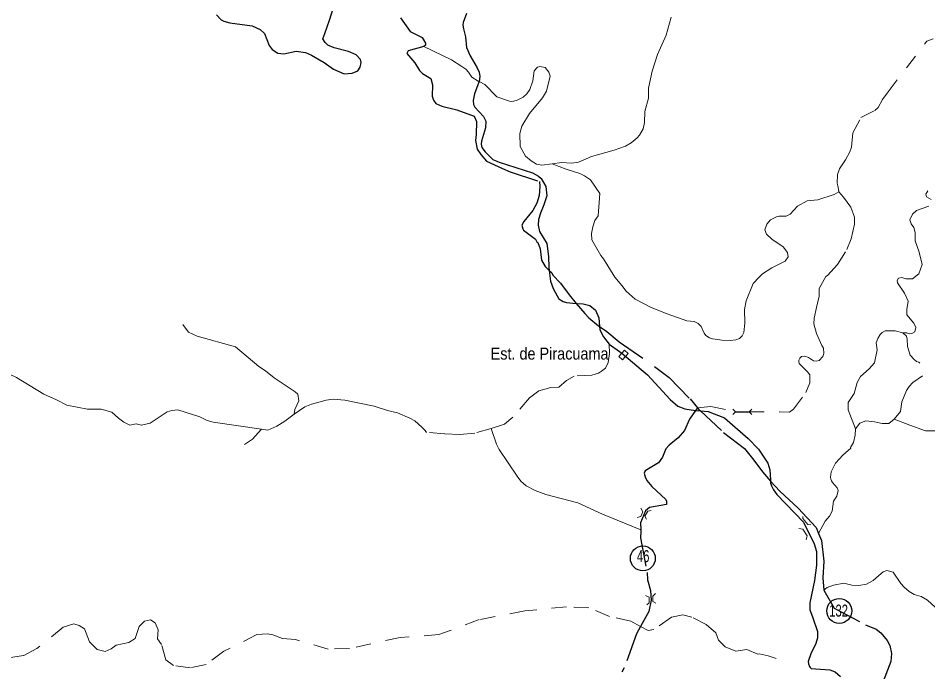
# Model space of a CAD drawing. Extents: x 423 to 448.8, y 7456.3 to 7484.
# Drawn here: x 434.76 to 440.83, y 7470.29 to 7474.65 of the extents above; entities that cross this region are included whole.
import ezdxf
from ezdxf.enums import TextEntityAlignment as Align

# ---------------------------------------------------------------- set-up
doc = ezdxf.new("R2010")
doc.units = 0
doc.header["$LTSCALE"] = 0.032
doc.linetypes.add('LONG_DASHED', pattern=[7.5, 6, -1.5])
doc.linetypes.add('MEDIUM_DASHED', pattern=[4.5, 3, -1.5])
for name, color, linetype, lineweight in [('11', 7, 'Continuous', 13), ('13', 7, 'Continuous', 25), ('15', 7, 'Continuous', 25), ('28', 7, 'Continuous', 25), ('31', 7, 'Continuous', 25), ('4', 7, 'LONG_DASHED', 25), ('6', 7, 'MEDIUM_DASHED', 13), ('7', 7, 'Continuous', 13)]:
    doc.layers.add(name, color=color, linetype=linetype, lineweight=lineweight)
doc.layers.add('61', color=7, linetype='Continuous')

msp = doc.modelspace()

# ---------------------------------------------------------------- linework, layer by layer
at = {"layer": '11'}
for points in [[(438.9162, 7471.3779), (438.93, 7471.3542), (438.9162, 7471.3236), (438.8915, 7471.3157)], [(438.9546, 7471.3058), (438.9428, 7471.3246), (438.9625, 7471.3591), (438.9852, 7471.364)], [(439.9969, 7471.3244), (439.9971, 7471.3106), (440.0308, 7471.269), (440.0512, 7471.2679)], [(439.9695, 7471.2426), (439.9963, 7471.2391), (440.0259, 7471.1952), (440.0195, 7471.168)], [(438.9477, 7470.7958), (438.9714, 7470.784), (438.9714, 7470.7475), (438.9566, 7470.7347)], [(439.0148, 7470.8086), (438.9961, 7470.7919), (438.9971, 7470.7554), (439.0158, 7470.7445)]]:
    msp.add_lwpolyline(points, dxfattribs=at)
at = {"layer": '13'}
for centre in [(438.9294, 7471.0434), (440.24, 7470.6931)]:
    msp.add_circle(centre, 0.083, dxfattribs=at)
at = {"layer": '15'}
for points in [[(436.0839, 7474.673), (436.1165, 7474.6386), (436.1328, 7474.6291), (436.1741, 7474.6188), (436.3235, 7474.5991), (436.3751, 7474.575), (436.4045, 7474.5469), (436.4353, 7474.4682), (436.4566, 7474.441), (436.4936, 7474.417), (436.534, 7474.4127), (436.6155, 7474.429), (436.6774, 7474.4196), (436.7186, 7474.4033), (436.8027, 7474.3543), (436.8654, 7474.3096), (436.9376, 7474.2775), (436.9889, 7474.2833), (437.0267, 7474.2982), (437.0436, 7474.3222), (437.0506, 7474.3541), (437.0466, 7474.375), (437.0162, 7474.4055), (436.9645, 7474.4284), (436.8689, 7474.4513), (436.8266, 7474.4688), (436.8087, 7474.4868), (436.7943, 7474.5116), (436.8072, 7474.5465), (436.838, 7474.6368), (436.868, 7474.7279)], [(437.7535, 7474.6807), (437.7315, 7474.6205), (437.7294, 7474.6042)], [(437.7294, 7474.6042), (437.7317, 7474.5789), (437.7466, 7474.5261), (437.7535, 7474.4548), (437.7779, 7474.3977), (437.8239, 7474.3191), (437.8367, 7474.2895), (437.842, 7474.2609), (437.8363, 7474.2266), (437.8357, 7474.2228), (437.8283, 7474.2048), (437.806, 7474.1445), (437.7981, 7474.0992), (437.7986, 7474.0746), (437.8081, 7474.0556), (437.8667, 7473.9928), (437.8807, 7473.9619), (437.8787, 7473.917), (437.8523, 7473.8279), (437.8515, 7473.8079), (437.8557, 7473.7866), (437.8769, 7473.7581), (437.9047, 7473.7299), (437.9288, 7473.7063), (437.9699, 7473.6888), (438.1924, 7473.6165), (438.2336, 7473.5951), (438.2499, 7473.5805), (438.2832, 7473.5264), (438.2894, 7473.4645), (438.2697, 7473.4036), (438.247, 7473.3479), (438.2327, 7473.3059), (438.2301, 7473.2679), (438.2404, 7473.2267), (438.2879, 7473.145), (438.3006, 7473.06), (438.3031, 7472.9863), (438.3054, 7472.9658), (438.3136, 7472.8943), (438.3315, 7472.8453), (438.3569, 7472.7962), (438.3691, 7472.777), (438.3982, 7472.7581), (438.4208, 7472.7508), (438.4853, 7472.7461), (438.492, 7472.7456), (438.5317, 7472.7432), (438.5766, 7472.7316), (438.6126, 7472.7001), (438.6357, 7472.6495), (438.6405, 7472.5912), (438.6423, 7472.5702), (438.6667, 7472.5221), (438.7042, 7472.4735), (438.7898, 7472.4142), (438.9602, 7472.2682), (439.1113, 7472.105), (439.1637, 7472.0597), (439.2095, 7472.0417), (439.2815, 7472.0304), (439.3137, 7472.0277), (439.3653, 7472.0235), (439.4733, 7471.9812), (439.6318, 7471.8448), (439.7014, 7471.7717), (439.7631, 7471.6803), (439.7775, 7471.6352), (439.7815, 7471.5689), (439.7818, 7471.5602), (439.7822, 7471.5471), (439.7847, 7471.5356), (439.7883, 7471.5274), (439.8005, 7471.5006), (439.8229, 7471.4699), (440.0013, 7471.285), (440.0732, 7471.1414), (440.087, 7471.0899), (440.088, 7470.9977), (440.0741, 7470.8958), (440.0432, 7470.7463), (440.044, 7470.6999), (440.0604, 7470.6528), (440.0947, 7470.5548), (440.0938, 7470.5144), (440.0844, 7470.4766), (440.0492, 7470.4062), (440.032, 7470.3555), (440.0346, 7470.3392), (440.042, 7470.3227), (440.0465, 7470.3147), (440.0528, 7470.3085), (440.1763, 7470.3006), (440.2123, 7470.2868), (440.2492, 7470.2546)]]:
    msp.add_lwpolyline(points, dxfattribs=at)
at = {"layer": '28'}
msp.add_lwpolyline([(438.7687, 7472.3921), (438.8069, 7472.4344), (438.832, 7472.4117), (438.7938, 7472.3694)], close=True, dxfattribs=at)
at = {"layer": '31'}
for p, q in [((439.5469, 7472.0219), (439.5294, 7472.0396)), ((439.6394, 7472.0219), (439.6571, 7472.0396)), ((439.5294, 7472.0043), (439.5469, 7472.0219)), ((439.5469, 7472.0219), (439.6394, 7472.0219)), ((439.6571, 7472.0043), (439.6394, 7472.0219))]:
    msp.add_line(p, q, dxfattribs=at)
at = {"layer": '4'}
for points in [[(437.312, 7474.6514), (437.3773, 7474.5613), (437.4572, 7474.5218), (437.4787, 7474.4823), (437.4787, 7474.4702), (437.4691, 7474.4617), (437.3636, 7474.4316), (437.3542, 7474.4133), (437.4086, 7474.3522), (437.4383, 7474.3002), (437.4589, 7474.2813), (437.5147, 7474.2478), (437.525, 7474.204), (437.5233, 7474.1284), (437.5319, 7474.1027), (437.5482, 7474.0812), (437.5878, 7474.0614), (437.6891, 7474.0374), (437.8033, 7473.9962), (437.8187, 7473.9593), (437.8174, 7473.8738), (437.8129, 7473.8338), (437.8245, 7473.7756), (437.849, 7473.7396), (437.8853, 7473.6949), (437.9939, 7473.6458), (438.0446, 7473.6236), (438.2396, 7473.5599), (438.2419, 7473.5267), (438.237, 7473.4654), (438.2216, 7473.4156), (438.1958, 7473.3658), (438.1348, 7473.2919), (438.1219, 7473.2679), (438.1288, 7473.2438), (438.1331, 7473.2344), (438.213, 7473.1751), (438.2216, 7473.1579), (438.2293, 7473.1528), (438.2439, 7473.1099), (438.2524, 7473.0353), (438.2771, 7472.9919), (438.3054, 7472.9658), (438.3222, 7472.9503), (438.3289, 7472.9346), (438.3796, 7472.8814), (438.438, 7472.8024), (438.4853, 7472.7461), (438.5419, 7472.6787), (438.5685, 7472.6503), (438.6329, 7472.5963), (438.6405, 7472.5912), (438.6901, 7472.5585), (438.7721, 7472.4897), (439.0074, 7472.3257), (439.1045, 7472.2501), (439.2444, 7472.1084), (439.2944, 7472.0483)], [(439.2942, 7472.0483), (439.2815, 7472.0304), (439.2417, 7471.9739), (439.2078, 7471.8982), (439.1661, 7471.8487), (439.1044, 7471.7993), (439.083, 7471.776), (439.0606, 7471.7203), (439.0332, 7471.6824), (438.9447, 7471.6292), (438.9387, 7471.612), (438.9438, 7471.588), (438.9559, 7471.5639), (438.9894, 7471.5227), (439.0821, 7471.4359), (439.0881, 7471.4248), (439.0873, 7471.4025), (438.9727, 7471.3829), (438.9463, 7471.3601), (438.9128, 7471.2818), (438.915, 7471.2343)], [(439.2944, 7472.0483), (439.3037, 7472.0371), (439.3137, 7472.0277), (439.4669, 7471.8843), (439.6086, 7471.7769), (439.6706, 7471.6991), (439.7273, 7471.6211), (439.7818, 7471.5602), (439.8431, 7471.4917), (439.9658, 7471.3787), (440.085, 7471.2503), (440.1025, 7471.2099), (440.1223, 7471.1642), (440.1359, 7471.0246), (440.1299, 7470.9147), (440.1376, 7470.8322), (440.2053, 7470.7115), (440.414, 7470.6004), (440.4855, 7470.5702), (440.5181, 7470.5462), (440.5602, 7470.4955), (440.5773, 7470.4612), (440.5876, 7470.4097), (440.5851, 7470.3547), (440.5207, 7470.1932)], [(438.915, 7471.2343), (438.9156, 7471.2221), (438.9146, 7471.1809), (438.9577, 7470.9493), (438.9611, 7470.9016), (438.9815, 7470.8301), (438.985, 7470.7653), (438.9688, 7470.6898), (438.914, 7470.5894), (438.8869, 7470.5397), (438.8051, 7470.3134), (438.7902, 7470.2846)]]:
    msp.add_lwpolyline(points, dxfattribs=at)
at = {"layer": '6'}
for points in [[(439.2942, 7472.0483), (439.2944, 7472.0483), (439.3822, 7472.0584), (439.5469, 7472.0219), (439.6394, 7472.0219), (439.8405, 7472.0216), (439.9083, 7472.0205), (439.9352, 7472.0398), (440.0159, 7472.1507), (440.0433, 7472.2145), (440.0433, 7472.2699), (440.0281, 7472.2893), (439.9838, 7472.3336), (439.973, 7472.3445), (439.9695, 7472.3575), (439.9697, 7472.3673), (439.9758, 7472.3801), (439.9883, 7472.3912), (440.0106, 7472.3928), (440.0347, 7472.384), (440.0678, 7472.3617), (440.0856, 7472.3593), (440.1061, 7472.3651), (440.1312, 7472.3908), (440.1369, 7472.4107), (440.134, 7472.4462), (440.1228, 7472.4639), (440.0872, 7472.545), (440.0707, 7472.6096), (440.0718, 7472.6473), (440.0878, 7472.7193), (440.105, 7472.7936), (440.1058, 7472.8445), (440.1511, 7472.9259), (440.1617, 7472.9312), (440.2287, 7473.0059), (440.2905, 7473.1064), (440.3197, 7473.1777), (440.3412, 7473.2756), (440.3421, 7473.3211), (440.3171, 7473.3881), (440.2673, 7473.4559), (440.2374, 7473.4897), (440.2369, 7473.4954), (440.23, 7473.5303), (440.2259, 7473.5492), (440.2277, 7473.6055), (440.2415, 7473.6435), (440.2813, 7473.7033), (440.3107, 7473.7576), (440.3216, 7473.7885), (440.3301, 7473.8836), (440.3843, 7473.9857), (440.4779, 7474.0346), (440.4993, 7474.054), (440.5282, 7474.1078), (440.5655, 7474.1592), (440.8247, 7474.496), (440.8659, 7474.5115)], [(438.7042, 7472.4735), (438.7063, 7472.4121), (438.6984, 7472.3507), (438.6796, 7472.3132), (438.6541, 7472.2942), (438.6324, 7472.2797), (438.5899, 7472.2673), (438.4713, 7472.2601), (438.419, 7472.2317), (438.3683, 7472.1869), (438.3145, 7472.1839), (438.2361, 7472.1615), (438.1735, 7472.1152), (438.0622, 7471.9866), (438.0055, 7471.9388), (437.9179, 7471.9118), (437.8078, 7471.879), (437.7083, 7471.8714), (437.6056, 7471.8761), (437.4863, 7471.8844), (437.4779, 7471.8963)], [(440.7956, 7472.2621), (440.7313, 7472.2186), (440.7054, 7472.1917), (440.6888, 7472.1647), (440.6582, 7472.0881), (440.6486, 7472.0243), (440.6068, 7471.972), (440.571, 7471.945), (440.5257, 7471.943), (440.474, 7471.956), (440.4172, 7471.9629), (440.3769, 7471.947), (440.349, 7471.9081), (440.347, 7471.8652), (440.3356, 7471.8164), (440.3147, 7471.7835), (440.3171, 7471.7804), (440.2642, 7471.7321), (440.2144, 7471.6783), (440.185, 7471.6215), (440.182, 7471.5851), (440.1828, 7471.5735), (440.1871, 7471.5615), (440.194, 7471.5499), (440.2265, 7471.5155), (440.2333, 7471.4969), (440.2244, 7471.46), (440.2013, 7471.4247), (440.1918, 7471.3586), (440.1754, 7471.3257), (440.1455, 7471.2928), (440.1025, 7471.2099)], [(439.8184, 7470.3756), (439.7651, 7470.3942), (439.7052, 7470.4056), (439.6969, 7470.4051), (439.6232, 7470.4345), (439.5496, 7470.4235), (439.4796, 7470.453), (439.4351, 7470.4973), (439.416, 7470.5457), (439.353, 7470.602), (439.2573, 7470.6515), (439.1954, 7470.6662), (439.1211, 7470.6504), (439.003, 7470.5683), (438.9658, 7470.5615), (438.914, 7470.5894), (438.8488, 7470.6245), (438.7058, 7470.656), (438.5697, 7470.7146), (438.4201, 7470.7213), (438.1409, 7470.6932), (437.8382, 7470.6347), (437.5692, 7470.5346), (437.3093, 7470.5166), (436.9728, 7470.4423), (436.8299, 7470.4377), (436.6127, 7470.5019), (436.526, 7470.5087), (436.4596, 7470.5334), (436.4257, 7470.54), (436.3538, 7470.5345), (436.1332, 7470.4242), (436.0163, 7470.3364), (435.9116, 7470.3128), (435.7979, 7470.3297), (435.7462, 7470.3657), (435.718, 7470.4692), (435.691, 7470.5075), (435.6955, 7470.5672), (435.6753, 7470.6144), (435.6448, 7470.6336), (435.6043, 7470.6257), (435.5683, 7470.5885), (435.5424, 7470.5086), (435.5008, 7470.4816), (435.4152, 7470.4647), (435.3826, 7470.44), (435.341, 7470.4231), (435.2881, 7470.4355), (435.2374, 7470.4873), (435.2048, 7470.5728), (435.1688, 7470.5964), (435.1331, 7470.6067), (435.0611, 7470.5842), (434.8867, 7470.4423), (434.7966, 7470.3951), (434.6151, 7470.368)]]:
    msp.add_lwpolyline(points, dxfattribs=at)
at = {"layer": '7'}
for points in [[(438.3251, 7473.6785), (438.3889, 7473.6856), (438.4537, 7473.6816), (438.5004, 7473.6887), (438.5857, 7473.7259), (438.7387, 7473.7677), (438.8134, 7473.7958), (438.8511, 7473.8166), (438.8906, 7473.851), (438.9069, 7473.8691), (438.9318, 7473.912), (438.9396, 7473.9523), (438.9431, 7474.0267), (438.9662, 7474.1155), (438.9662, 7474.1834), (438.9919, 7474.2959), (439.028, 7474.4075), (439.0856, 7474.5364), (439.1173, 7474.6558)], [(438.3251, 7473.6785), (438.2545, 7473.6676), (438.219, 7473.6758), (438.1838, 7473.6964), (438.1468, 7473.729), (438.1107, 7473.7926), (438.1082, 7473.8802), (438.1228, 7473.9292), (438.1727, 7474.0138), (438.2598, 7474.1181), (438.2869, 7474.1636), (438.3109, 7474.2632), (438.3014, 7474.289), (438.2774, 7474.3199), (438.2422, 7474.3277), (438.2267, 7474.3234), (438.2035, 7474.2993), (438.1958, 7474.2315), (438.1761, 7474.1739), (438.1554, 7474.1439), (438.1305, 7474.1224), (438.0867, 7474.101), (438.055, 7474.0941), (438.0395, 7474.0958), (437.9545, 7474.1258), (437.8749, 7474.2066), (437.8363, 7474.2266), (437.8296, 7474.2301), (437.7892, 7474.2563), (437.7657, 7474.2904), (437.7479, 7474.3094), (437.7226, 7474.3274), (437.6529, 7474.3712), (437.4691, 7474.4617)], [(440.2374, 7473.4897), (440.2068, 7473.4735), (440.0979, 7473.4368), (440.0257, 7473.4312), (439.9624, 7473.395), (439.9118, 7473.3409), (439.8851, 7473.3288), (439.8387, 7473.3288), (439.8207, 7473.3245), (439.7821, 7473.3031), (439.7563, 7473.2756), (439.7443, 7473.237), (439.7546, 7473.2069), (439.7898, 7473.1751), (439.8662, 7473.1227), (439.8946, 7473.0866), (439.8998, 7473.0574), (439.88, 7473.0282), (439.7906, 7472.9836), (439.7288, 7472.9441), (439.7048, 7472.9217), (439.6652, 7472.8791), (439.6181, 7472.7637), (439.6086, 7472.7045), (439.6095, 7472.6143), (439.6026, 7472.5524), (439.5923, 7472.5301), (439.5735, 7472.5118), (439.5509, 7472.502), (439.5125, 7472.4991), (439.4564, 7472.5011), (439.4294, 7472.5047), (439.3949, 7472.5089), (439.3746, 7472.5165), (439.3506, 7472.5323), (439.3375, 7472.5477), (439.3178, 7472.5908), (439.2992, 7472.6109), (439.2713, 7472.6243), (439.2226, 7472.6304), (439.0907, 7472.6753), (438.9851, 7472.719), (438.8789, 7472.7739), (438.8182, 7472.8268), (438.7884, 7472.8647), (438.7421, 7472.9201), (438.6679, 7473.0433), (438.65, 7473.0653), (438.5898, 7473.1706), (438.5873, 7473.212), (438.5953, 7473.2579), (438.6087, 7473.2993), (438.6306, 7473.3303), (438.6421, 7473.4805), (438.5799, 7473.5717), (438.5396, 7473.5972), (438.5087, 7473.6131), (438.4172, 7473.6411), (438.3251, 7473.6785)], [(440.8532, 7473.4396), (440.8219, 7473.4577), (440.8186, 7473.4759), (440.8318, 7473.4973)], [(440.6642, 7472.5492), (440.6902, 7472.5492), (440.7062, 7472.5433), (440.7237, 7472.546), (440.7439, 7472.5571), (440.7503, 7472.5842), (440.7371, 7472.6143), (440.6907, 7472.6701), (440.6907, 7472.7045), (440.6993, 7472.7612), (440.6753, 7472.8144), (440.6289, 7472.8822), (440.6263, 7472.8985), (440.6349, 7472.9149), (440.6384, 7472.9144), (440.6572, 7472.9192), (440.6852, 7472.9094), (440.7297, 7472.9094), (440.7708, 7472.9439), (440.7922, 7473.0065), (440.7741, 7473.0872), (440.7461, 7473.163), (440.7466, 7473.2181), (440.7379, 7473.2535), (440.7203, 7473.2762), (440.7115, 7473.3046), (440.728, 7473.3408), (440.7544, 7473.3655), (440.8367, 7473.3952)], [(436.6023, 7472.0069), (436.6027, 7472.009), (436.6083, 7472.0377), (436.6343, 7472.0957), (436.6269, 7472.1402), (436.6096, 7472.1563), (436.4688, 7472.2489), (436.412, 7472.2958), (436.3663, 7472.3255), (436.2106, 7472.4552), (435.955, 7472.5268), (435.8982, 7472.554), (435.8599, 7472.6058)], [(440.6642, 7472.5492), (440.6125, 7472.5632), (440.5458, 7472.5622), (440.5266, 7472.5507), (440.5139, 7472.5373), (440.4965, 7472.5119), (440.4865, 7472.483), (440.4925, 7472.4351), (440.4761, 7472.3499), (440.4398, 7472.3096), (440.3815, 7472.2587), (440.3592, 7472.2184), (440.3395, 7472.1453), (440.3, 7472.0852), (440.3, 7472.0354), (440.349, 7471.9081)], [(440.7767, 7472.346), (440.7714, 7472.3541), (440.756, 7472.3575), (440.7397, 7472.3712), (440.713, 7472.4013), (440.6956, 7472.4579), (440.6936, 7472.5068), (440.6885, 7472.5274), (440.6642, 7472.5492)], [(436.385, 7471.9059), (436.0625, 7471.953), (436.0229, 7471.9633), (435.9729, 7471.9884), (435.8262, 7472.0354), (435.7859, 7472.032), (435.7558, 7472.0226), (435.6429, 7471.9468), (435.5832, 7471.9339), (435.5479, 7471.9424), (435.5071, 7471.9325), (435.4662, 7471.9534), (435.4304, 7471.9793), (435.3866, 7472.0202), (435.3154, 7472.0407), (435.2229, 7472.0387), (435.086, 7472.0662), (435.0164, 7472.1031), (434.9333, 7472.1396), (434.7506, 7472.251), (434.6665, 7472.2914), (434.6416, 7472.2954), (434.6324, 7472.3034)], [(437.4779, 7471.8963), (437.4546, 7471.9186), (437.4074, 7471.9615), (437.3741, 7471.9802), (437.2914, 7472.0151), (437.2267, 7472.0301), (437.1376, 7472.0596), (436.9402, 7472.1007), (436.8629, 7472.1067), (436.8165, 7472.1007), (436.7186, 7472.0732), (436.6739, 7472.0552), (436.6023, 7472.0069)], [(436.6023, 7472.0069), (436.5409, 7471.9589), (436.4871, 7471.926), (436.4269, 7471.9006), (436.385, 7471.9059)], [(440.6068, 7471.972), (440.7109, 7471.9323), (440.8152, 7471.896), (440.9184, 7471.8959)], [(436.2712, 7471.803), (436.3243, 7471.8388), (436.3832, 7471.9039), (436.385, 7471.9059)], [(437.9179, 7471.9118), (437.9525, 7471.8055), (437.9704, 7471.7706), (438.091, 7471.5923), (438.1159, 7471.5596), (438.1512, 7471.527), (438.2104, 7471.4961), (438.2817, 7471.4712), (438.4955, 7471.4145), (438.6613, 7471.3398), (438.915, 7471.2343)], [(440.8794, 7470.7171), (440.8286, 7470.764), (440.7873, 7470.7885), (440.7405, 7470.8034), (440.7057, 7470.8234), (440.6738, 7470.8523), (440.6505, 7470.875), (440.5988, 7470.951), (440.5584, 7470.9628), (440.5338, 7470.9538), (440.5205, 7470.9431), (440.4668, 7470.8953), (440.4226, 7470.8707), (440.3707, 7470.8619), (440.323, 7470.8659), (440.2712, 7470.8778), (440.2004, 7470.866), (440.1591, 7470.8485), (440.1376, 7470.8322)]]:
    msp.add_lwpolyline(points, dxfattribs=at)

# ---------------------------------------------------------------- texts
at = {"layer": '61', "width": 0.9}
msp.add_text('Est. de Piracuama', height=0.08, dxfattribs=at).set_placement((438.7003, 7472.3707), align=Align.RIGHT)
at = {"layer": '61', "width": 0.7}
for s, p in [('46', (438.9316, 7471.0188)), ('132', (440.2355, 7470.6552))]:
    msp.add_text(s, height=0.08, dxfattribs=at).set_placement(p, align=Align.CENTER)

doc.saveas('drawing.dxf')
